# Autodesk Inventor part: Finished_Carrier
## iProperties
Created: 2004-06
Part Number: Finished_Carrier
Document SubType Name: Modeling
Designer: rak
Manufacturer: Standard
Standards Organization: Custom
Author: rak
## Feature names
1. Extrusion1
2. Extrusion2
3. Circular Pattern1
4. Fillet1
5. Fillet2
6. Hole1
7. Circular Pattern2
8. Revolution1
